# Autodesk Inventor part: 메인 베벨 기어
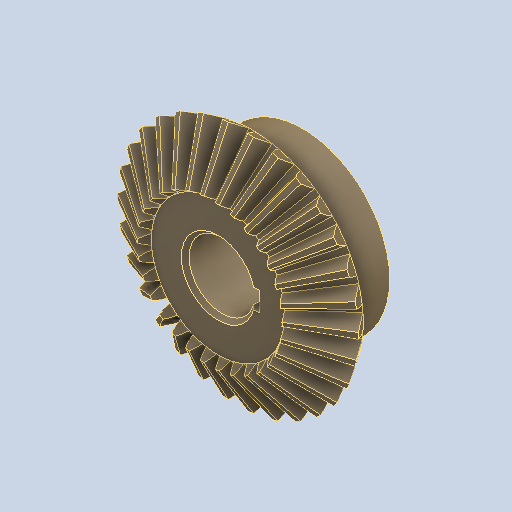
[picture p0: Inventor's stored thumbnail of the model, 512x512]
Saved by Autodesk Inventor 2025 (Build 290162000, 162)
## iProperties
Created: 2024-07
Part Number: 메인 베벨 기어
Material: 강철, 탄소
Document SubType Name: Modeling
Designer: SAMSUNG
Density: 7.87 g/cm^3
Appearance: 기본값
Author: jhkim
Revision Number: 1
Sending System: Autodesk Inventor 2025
Preprocessor: ST-DEVELOPER v20
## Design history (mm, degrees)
feature "Solid1"
node "솔리드1"
